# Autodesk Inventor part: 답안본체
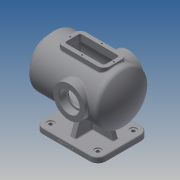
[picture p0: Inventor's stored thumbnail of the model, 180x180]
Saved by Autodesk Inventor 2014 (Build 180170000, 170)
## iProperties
Created: 2021-11
Part Number: 답안본체
Material: Generic
Document SubType Name: Modeling
Designer: kb542
Density: 1 g/cm^3
Appearance: Default
Mass: 1311.09 g
Surface Area: 2405.55 cm^2
Volume: 1311.09 cm^3
Author: kb542
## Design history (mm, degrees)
sketch "스케치1"
  geometry: L1 (0, 0)-(210, 0); L2 (20, 65)-(181.239, 65); L3 (10, 55)-(10, 47.5); L4 (10, 47.5)-(0, 47.5); L5 (0, 47.5)-(0, 32.5); L6 (0, 32.5)-(25, 32.5); L7 (25, 32.5)-(25, 52); L8 (28, 55)-(179.75, 55); A1 r 100 centre (110, 0) between (210, 0) and (189.154, 61.111); A2 r 90 centre (110, 0) between (200, 0) and (182.155, 53.793); A3 r 10 centre (181.239, 55) between (189.154, 61.111) and (181.239, 65); A4 r 3 centre (179.75, 52) between (182.155, 53.793) and (179.75, 55); A5 r 10 centre (20, 55) between (20, 65) and (10, 55); A6 r 3 centre (28, 52) between (28, 55) and (25, 52); 3 further points
  constraints: 16 end point, 14 point on circle, 8 tangent, 6 centre point, 6 point on line, 5 parallel, 2 perpendicular, 1 concentric, 1 horizontal, 1 vertical alignment
  dimensions: "d0" = 210 distance of L1.start L1.end; "d1" = 100 radius of A1; "d2" = 10 distance between parallel lines of L2 L8; "d3" = 10 radial gap between concentric circles of A1 A2; "d4" = 130 diameter of L2 L1; "d5" = 65 diameter of L6 L1; "d6" = 95 diameter of L4 L1; "d7" = 10 distance between parallel lines of L3 L5; "d8" = 10 radius of A3; "d9" = 3 radius of A4; "d11" = 25 distance of L5.end L6.end; "d128" = 10 radius of A5; "d129" = 3 radius of A6
revolve "회전1" sketch "스케치1" stored, may be unused: angle "d12" = 90 deg
node "작업 평면1"
sketch "스케치2"
  geometry: L1 (50, 65)-(170, 65); L2 (190, 45)-(190, -45); L3 (170, -65)-(50, -65); L4 (30, -45)-(30, 45); L5 (181.239, -65)-(181.239, 65) reference; L6 (20, -65)-(20, 65) reference; L7 (10, -47.5)-(10, 47.5) reference; L8 (0, -47.5)-(0, 47.5) reference; A1 r 20 centre (170, 45) between (190, 45) and (170, 65); A2 r 20 centre (170, -45) between (170, -65) and (190, -45); A3 r 20 centre (50, -45) between (30, -45) and (50, -65); A4 r 20 centre (50, 45) between (50, 65) and (30, 45); 6 further points
  constraints: 8 end point, 8 point on circle, 8 tangent, 6 point on line, 4 centre point, 3 equal radius, 2 midpoint, 2 parallel, 1 horizontal, 1 horizontal alignment, 1 perpendicular
  dimensions: "d14" = 160 distance of point (30, 65) point (190, 65); "d15" = 30 distance between parallel lines of L4 L8; "d16" = 130 distance of point (190, 65) point (190, -65); "d17" = 20 radius of A1
extrude "돌출1" join sketch "스케치2" distance "d18" = 14; taper "d19" = 0 deg
sketch "스케치3"
  geometry: C1 r 9 at (50, 45); C2 r 9 at (50, -45); C3 r 9 at (170, -45); C4 r 9 at (170, 45); A1 r 20 centre (170, 45) between (190, 45) and (170, 65) reference; A2 r 20 centre (50, 45) between (50, 65) and (30, 45) reference; A3 r 20 centre (50, -45) between (30, -45) and (50, -65) reference; A4 r 20 centre (170, -45) between (170, -65) and (190, -45) reference; 1 further point
  constraints: 4 centre point, 3 coincident, 3 equal radius, 1 concentric, 1 horizontal alignment
  dimensions: "d20" = 18 diameter of C2
hole "구멍1" sketch "스케치3" at (50, -45), (170, -45), (50, 45), (170, 45) diameter "d21" = 9; stored, may be unused: countersink angle "d25" = 90 deg, drill point angle "d27" = 118 deg; dims "d22" = 6, "d23" = 18, "d24" = 2, "d26" = 8
sketch "스케치4"
  geometry: L1 (170, 65)-(50, 65) reference; L2 (30, 45)-(30, -45) reference; L3 (103, 7)-(117, 7); L4 (117, 7)-(117, -7); L5 (117, -7)-(103, -7); L6 (103, -7)-(103, 7); 1 further point
  constraints: 8 end point, 2 parallel, 1 horizontal, 1 perpendicular
  dimensions: "d28" = 14 distance of L3.start L3.end; "d29" = 14 distance of L5.end L3.start; "d30" = 73 distance between parallel lines of L6 L2; "d31" = 58 distance between parallel lines of L1 L3
extrude "돌출2" join sketch "스케치4" stored distance "d32" = 14; taper "d33" = 0 deg
sketch "스케치5"
  geometry: L1 (-157.123, -64.622)-(-170, -100); L2 (-170, -114)-(-50, -114) reference; L3 (-170, -114)-(-170, -100) reference; L4 (-50, -100)-(-170, -100) reference; L5 (-50, -114)-(-50, -100) reference; L6 (-110, -114)-(-110, -64.622); L7 (-170, -100)-(-190, -100) reference; L8 (-179.75, 55)-(-179.75, -55) reference; L9 (-20, 65)-(-20, -65) reference; L10 (-181.239, 65)-(-181.239, -65) reference; L11 (-117, -64.622)-(-117, -64.622) reference; L12 (-117, -64.622)-(-103, -64.622) reference; L13 (-103, -64.622)-(-103, -64.622) reference; L14 (-103, -64.622)-(-117, -64.622) reference; 4 further points
  constraints: 4 end point, 3 midpoint, 1 horizontal alignment, 1 parallel, 1 point on line
  dimensions: "d34" = 120 diameter of L1.end L6; "d35" = 110 deg angle of L7 L1
feature "리브1" sketch "스케치5" dims "d37" = 1, "d38" = 14, "d39" = 0, "d40" = 0, "d41" = 1, "d42" = 1
node "작업 평면2"
sketch "스케치6"
  geometry: L1 (14, 95)-(58.485, 78.809); L2 (14, 90)-(14, 110) reference; L3 (0, 90)-(0, 0) reference; L4 (0, 90)-(14, 90) reference; L5 (14, 0)-(14, 90) reference; L6 (0, 0)-(14, 0) reference; L7 (0, 45)-(114, 45); C1 r 61.111 at (114, 45) reference; 1 further point
  constraints: 4 end point, 1 midpoint, 1 parallel, 1 point on line, 2 other
  dimensions: "d43" = 110 deg angle of L2 L1; "d44" = 100 diameter of L1.start L7
feature "리브2" sketch "스케치6" dims "d45" = 1, "d46" = 14, "d47" = 0, "d48" = 0, "d49" = 1, "d50" = 1
node "작업 평면3"
node "작업 평면4"
sketch "스케치8"
  geometry: L1 (65, 30)-(155, 30); L2 (170, 15)-(170, -15); L3 (155, -30)-(65, -30); L4 (50, -15)-(50, 15); A1 r 15 centre (65, -15) between (50, -15) and (65, -30); A2 r 15 centre (155, -15) between (155, -30) and (170, -15); A3 r 15 centre (155, 15) between (170, 15) and (155, 30); A4 r 15 centre (65, 15) between (65, 30) and (50, 15); 2 further points
  constraints: 8 end point, 8 point on circle, 8 tangent, 4 centre point, 3 equal radius, 2 parallel, 1 horizontal, 1 horizontal alignment, 1 midpoint, 1 perpendicular
  dimensions: "d62" = 15 radius of A1; "d63" = 120 distance between parallel lines of L2 L4; "d64" = 50 distance from line of point (0, 0) L4; "d65" = 60 distance between parallel lines of L3 L1
extrude "돌출3" join sketch "스케치8" stored distance "d66" = 14; taper "d67" = 0 deg
sketch "스케치9"
  geometry: L1 (65, -30)-(155, -30) reference; L2 (170, -15)-(170, 15) reference; L3 (155, 30)-(65, 30) reference; L4 (50, 15)-(50, -15) reference; L5 (160, 15)-(160, -15); L6 (155, -20)-(65, -20); L7 (60, -15)-(60, 15); L8 (65, 20)-(155, 20); A1 r 15 centre (155, -15) between (155, -30) and (170, -15) reference; A2 r 15 centre (155, 15) between (170, 15) and (155, 30) reference; A3 r 15 centre (65, 15) between (65, 30) and (50, 15) reference; A4 r 15 centre (65, -15) between (50, -15) and (65, -30) reference; A5 r 5 centre (155, 15) between (160, 15) and (155, 20); A6 r 5 centre (155, -15) between (155, -20) and (160, -15); A7 r 5 centre (65, -15) between (60, -15) and (65, -20); A8 r 5 centre (65, 15) between (65, 20) and (60, 15); 1 further point
  constraints: 8 end point, 8 point on circle, 4 centre point, 7 other
  dimensions: "d68" = 10 distance between parallel lines of L2 L5
extrude "돌출4" cut sketch "스케치9" stored distance "d69" = 14; taper "d70" = 0 deg
sketch "스케치10"
  geometry: C1 r 40 at (-127, 0); 1 further point
  constraints: 1 centre point, 1 horizontal alignment
  dimensions: "d71" = 80 diameter of C1; "d72" = 127 distance of point (0, 0) C1.centre
extrude "돌출5" join sketch "스케치10" stored distance "d73" = 14; taper "d74" = 0 deg
hole "구멍2" diameter "d77" = 42; stored, may be unused: countersink angle "d81" = 90 deg, drill point angle "d83" = 118 deg; dims "d75" = 10, "d76" = 10, "d78" = 6, "d79" = 52, "d80" = 18, "d82" = 8
sketch "스케치11"
  geometry: L1 (120, 0)-(0, 0) reference; L2 (34.543, 8.002)-(85.457, 8.002); L3 (85.457, 8.002)-(85.457, 1.998); L4 (85.457, 1.998)-(34.543, 1.998); L5 (34.543, 1.998)-(34.543, 8.002); L6 (53, 58.485)-(67, 58.485) reference; 4 further points
  constraints: 3 midpoint, 1 vertical alignment, 2 other
  dimensions: "d84" = 5 distance from line of L1 point (34.543, 5)
feature "엠보싱1" sketch "스케치11" dims "d0" = 210, "d1" = 100, "d2" = 10, "d3" = 10, "d4" = 130, "d5" = 65, "d6" = 95, "d7" = 10, "d8" = 10, "d9" = 3, "d11" = 25, "d85" = 0.5, "d86" = 0, "d128" = 10, "d129" = 3
fillet "모깎기1" dims "d87" = 3
fillet "모깎기2" dims "d88" = 3
fillet "모깎기3" dims "d89" = 3
sketch "스케치12" dims "d90" = 80
  geometry: C1 r 32.5 at (0, 0) reference; C2 r 47.5 at (0, 0) reference; 2 further points
  constraints: 2 vertical alignment, 1 coincident, 2 other
hole "구멍3" sketch "스케치12" at (0, 40) diameter "d91" = 3.459; stored, may be unused: countersink angle "d95" = 90 deg, drill point angle "d97" = 118 deg; dims "d92" = 11, "d93" = 52, "d94" = 18, "d96" = 13
sketch "스케치13" dims "d101" = 65
  geometry: C1 r 26 at (0, 0) reference; C2 r 40 at (0, 0) reference; 3 further points
  constraints: 2 vertical alignment, 1 coincident, 2 other
hole "구멍4" sketch "스케치13" at (0, 32.5) diameter "d102" = 3.459; stored, may be unused: countersink angle "d106" = 90 deg, drill point angle "d108" = 118 deg; dims "d103" = 11, "d104" = 52, "d105" = 18, "d107" = 13
chamfer "모따기1" distance "d112" = 1; stored, may be unused: second distance "d113" = 2, angle "d114" = 45 deg
fillet "모깎기4" dims "d115" = 0.3
sketch "스케치14"
  geometry: L1 (170, -15)-(170, 15) reference; L2 (155, 30)-(65, 30) reference; L3 (50, 15)-(50, -15) reference; L4 (110, 25)-(110, -25); 8 further points
  constraints: 5 midpoint, 3 horizontal alignment, 2 end point, 2 vertical alignment, 1 parallel
  dimensions: "d116" = 55 horizontal distance of L4.start point (55, 0); "d117" = 55 horizontal distance of L4.start point (165, 0); "d118" = 50 distance of L4.start L4.end
hole "구멍5" sketch "스케치14" at (110, -25), (165, 0), (110, 25), (55, 0) diameter "d119" = 3.459; stored, may be unused: countersink angle "d123" = 90 deg, drill point angle "d125" = 118 deg; dims "d120" = 9, "d121" = 52, "d122" = 18, "d124" = 11
fillet "모깎기5" dims "d126" = 3
fillet "모깎기6" dims "d127" = 3
node "솔리드1"
mirror "대칭1"
mirror "대칭2"
mirror "대칭4"
pattern_circular "원형 패턴1" dims angle "d99" = 360 deg
pattern_circular "원형 패턴2" dims angle "d110" = 360 deg
mirror "대칭5"
node "투영된 루프1"
node "투영된 루프2"
node "투영된 루프3"
node "투영된 루프4"
node "투영된 루프5"
node "투영된 루프6"
other parameters: "d13" = -114, "d60" = 75
